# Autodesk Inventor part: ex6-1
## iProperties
Shininess: 64.0
Length Units: 11272
Angle Units: 11279
Time Units: 11290
Mass Units: 11286
Length Display Precision: 3
Angle Display Precision: 2
Compacted: True
Part Number: ex6-1
Document SubType Name: Modeling
Created: 2002-11
Designer: Elise Moss
Density: 0.0
Volumn: 0.0
Area: 0.0
PropertySet Name: Model Information
Control State: 0
Master: False
Checked Out: False
Author: Elise Moss
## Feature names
1. Extrusion1
2. Extrusion2
3. Extrusion3
